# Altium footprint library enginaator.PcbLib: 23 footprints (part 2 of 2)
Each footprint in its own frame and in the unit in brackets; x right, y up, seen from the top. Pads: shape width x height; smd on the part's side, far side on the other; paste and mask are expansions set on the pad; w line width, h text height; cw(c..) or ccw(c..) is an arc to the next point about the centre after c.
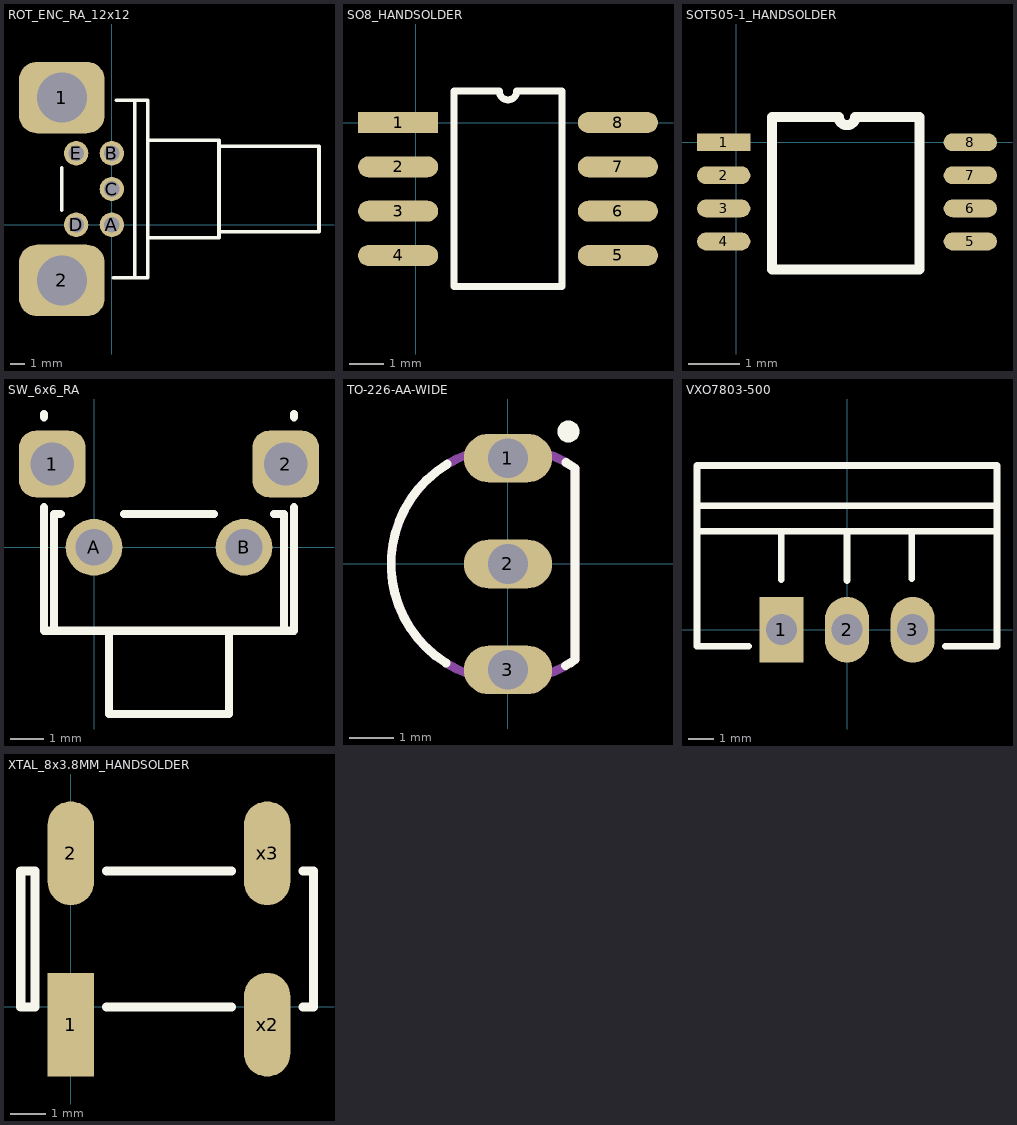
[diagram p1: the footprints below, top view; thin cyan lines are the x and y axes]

## ROT_ENC_RA_12x12 [mm]
pads (7):
  rrect50% 6x5 hole 3.5: 1(-3.5,8.9) 2(-3.5,-3.9)
  round 1.7 hole 1.1: A(0,0) B(0,5) C(0,2.5) D(-2.5,0) E(-2.5,5)
Top Overlay:
  lines w0.254: -3.5,1 -3.5,4 ; 0.1,-3.7 2.5,-3.7 2.5,8.7 0.3,8.7 ; 1.6,-3.7 1.6,8.7 ; 2.5,-0.9 7.5,-0.9 7.5,5.9 2.5,5.9 ; 7.5,-0.5 14.5,-0.5 14.5,5.5 7.5,5.5

## SO8_HANDSOLDER [mm]
pads (8):
  rect 2.3x0.6 smd: 1(-0.5,0)
  oval 2.3x0.6 smd: 2(-0.5,-1.27) 3(-0.5,-2.54) 4(-0.5,-3.81) 5(5.8,-3.81) 6(5.8,-2.54) 7(5.8,-1.27) 8(5.8,0)
Top Overlay:
  lines w0.2: 1.1,-4.7 1.1,0.9 2.4,0.9 ccw(c2.65,0.9) 2.9,0.9 4.2,0.9 4.2,-4.7 1.1,-4.7

## SOT505-1_HANDSOLDER [mm]
pads (8):
  rect 1.05x0.35 smd: 1(-0.25,0)
  oval 1.05x0.35 smd: 2(-0.25,-0.65) 3(-0.25,-1.3) 4(-0.25,-1.95) 5(4.6,-1.95) 6(4.6,-1.3) 7(4.6,-0.65) 8(4.6,0)
Top Overlay:
  lines w0.2: 0.7,-2.5 0.7,0.5 2.013,0.5 ccw(c2.175,0.5) 2.337,0.5 3.6,0.5 3.6,-2.5 0.7,-2.5

## SW_6x6_RA [mm]
pads (4):
  rrect50% 2x2 hole 1.3: 1(-1.25,2.5) 2(5.75,2.5)
  round 1.7 hole 1.1: A(0,0) B(4.5,0)
Top Overlay:
  lines w0.254: -1.5,1.2 -1.5,1 -1.5,-2.5 6,-2.5 6,1 6,1.2 ; -1.5,3.9 -1.5,4 ; -1.2,-2.5 -1.2,1 -1,1 ; 0.45,-2.55 0.45,-5 4.05,-5 4.05,-2.55 ; 0.9,1 3.6,1 ; 5.4,1 5.7,1 5.7,-2.5 ; 6,3.9 6,4

## TO-226-AA-WIDE [mm] "TO, Flat Index; 3 In-Line, Axial Leads; Body Dia. 4.8mm; Leads 0.55 x 0.51 mm (max)"
height 5.33
pads (3):
  oval 2x1.1 hole 0.9: 1(0,2.4) 2(0,0) 3(0,-2.4)
Top Overlay:
  circle w0.25: c1.371,3.003 r0.125
  lines w0.2: -1.407,-2.246 cw(c0,0) -1.378,2.264 ; 1.304,-2.307 ccw(c0,0) 1.52,-2.171 1.52,2.171 ccw(c0,0) 1.315,2.301
Mechanical 13:
  lines w0.2: 1.52,-2.171 cw(c0,0) 1.52,2.171 1.52,-2.171
Mechanical 15:
  lines w0.1: -0.5,0 0.5,0 ; 0,-0.5 0,0.5
3D body: height 5.33, standoff 0, extent -2.651,-2.661 1.52,2.661

## VXO7803-500 [mm]
pads (3):
  rect 1.7x2.54 hole 1.2: 1(-2.54,0)
  oval 1.7x2.54 hole 1.2: 2(0,0) 3(2.54,0)
Top Overlay:
  lines w0.254: -5.8,3.8 5.8,3.8 ; -5.8,4.8 5.8,4.8 ; -3.81,-0.635 -5.8,-0.635 -5.8,6.35 5.8,6.35 5.8,-0.635 3.81,-0.635
  lines w0.256: -2.54,1.94 -2.54,3.7 ; 0,1.9 0,3.8 ; 2.5,1.98 2.5,3.8

## XTAL_8x3.8MM_HANDSOLDER [mm]
pads (4):
  rect 1.3x2.9 smd: 1(0,-0.5)
  oval 1.3x2.9 smd: 2(0,4.3) x2(5.5,-0.5) x3(5.5,4.3)
Top Overlay:
  lines w0.254: 1,0 4.5,0 ; 1,3.8 4.5,3.8 ; 6.5,0 6.8,0 6.8,3.8 6.5,3.8 ; -1.4,0 -1,0 -1,3.8 -1.4,3.8 -1.4,0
